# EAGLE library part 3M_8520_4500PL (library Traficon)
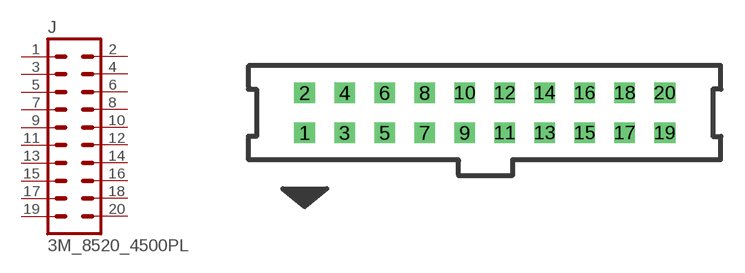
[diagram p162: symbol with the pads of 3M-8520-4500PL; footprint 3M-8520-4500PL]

Designator prefix J

## 3M_8520_4500PL  [3M-8520-4500PL]
1  1  pas
2  2  pas
3  3  pas
4  4  pas
5  5  pas
6  6  pas
7  7  pas
8  8  pas
9  9  pas
10  10  pas
11  11  pas
12  12  pas
13  13  pas
14  14  pas
15  15  pas
16  16  pas
17  17  pas
18  18  pas
19  19  pas
20  20  pas

## Footprint 3M-8520-4500PL (pad centres in mm)
drill 0.813 square: 1 -11.43,-1.27; 2 -11.43,1.27; 3 -8.89,-1.27; 4 -8.89,1.27; 5 -6.35,-1.27; 6 -6.35,1.27; 7 -3.81,-1.27; 8 -3.81,1.27; 9 -1.27,-1.27; 10 -1.27,1.27; 11 1.27,-1.27; 12 1.27,1.27; 13 3.81,-1.27; 14 3.81,1.27; 15 6.35,-1.27; 16 6.35,1.27; 17 8.89,-1.27; 18 8.89,1.27; 19 11.43,-1.27; 20 11.43,1.27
